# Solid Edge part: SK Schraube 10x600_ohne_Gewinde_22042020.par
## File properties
Author: fknapp
Template: Normal.par
Last saved by: fknapp
Revision: 36
Application: Solid Edge
Username: fknapp
Material: Aluminium
Genauigkeit: 0,99
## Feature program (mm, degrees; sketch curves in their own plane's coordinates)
sketch for "unnamed RevolvedProtrusion 1" plane through (0, 0, 0) normal (0, 0, 1) x-axis (1, 0, 0)
  line (0, 54) -> (9, 54)
  line (9, 54) -> (9, 53)
  line (9, 53) -> (5, 49)
  line (5, 49) -> (5, 46.3)
  line (5, 46.3) -> (4.7548, 46.3)
  arc centre (4.7548, 44.6952) radius 1.6048 from (4.7548, 46.3) to (3.15, 44.6952) ccw
  line (3.15, 44.6952) -> (3.15, 42)
  line (3.15, 42) -> (5, 42)
  line (5, -533) -> (5, 42)
  line (0.5, -546) -> (5, -533)
  line (0, -546) -> (0.5, -546)
revolve "unnamed RevolvedProtrusion 1" add full turn 360 deg about sketch line (0, 54) -> (0, -546)
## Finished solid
Body 1: solid body, 11 faces, 10 edges, 0 vertices.
  Faces by surface: cylinder 4, plane 4, cone 2, torus 1
  Edges by curve: circle 10
Bounding box of the edges (mm; curved faces can reach further): 18.000 x 600.000 x 18.000, from (-9, -546, -9) to (9, 54, 9).
Cylindrical faces by radius (mm): R3.15 x1, R5 x2, R9 x1
Conical faces (half-angle, radius in mm at the cone's reference point): 19.0935 deg R5 x1, 45 deg R9 x1
Toroidal faces (ring radius, tube radius in mm): R4.7548 r1.6048 x1
Planar faces by outward normal: +y 2, -y 2
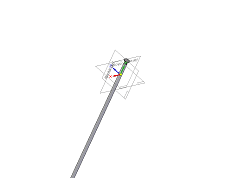
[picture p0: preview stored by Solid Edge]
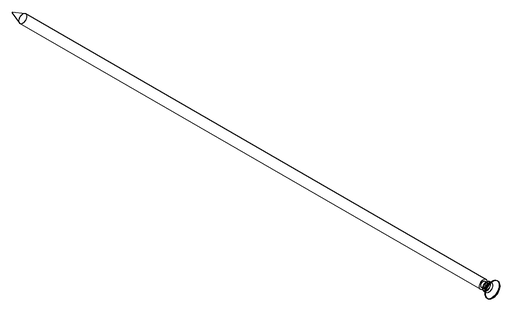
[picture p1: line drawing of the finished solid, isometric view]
